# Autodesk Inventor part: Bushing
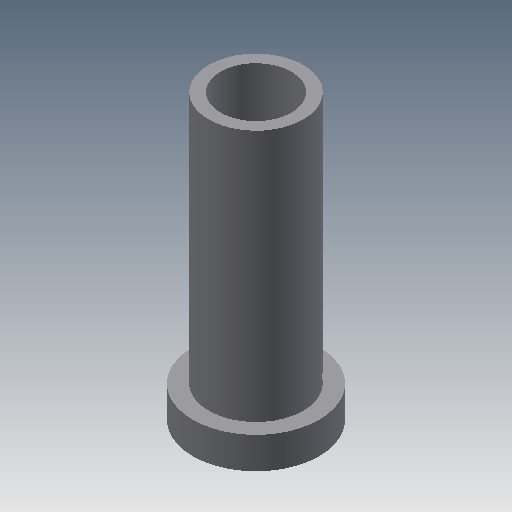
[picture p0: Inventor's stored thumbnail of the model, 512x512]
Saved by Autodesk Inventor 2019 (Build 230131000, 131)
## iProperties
Shininess: 77.0
Length Units: 11269
Angle Units: 11279
Time Units: 11290
Mass Units: 11283
Length Display Precision: 3
Angle Display Precision: 2
Created: 2002-02
Part Number: Bushing
Document SubType Name: Modeling
Designer: ***
Density: 1 g/cm^3
Material: Generic
Appearance: Default
Density: 0.0
Volumn: 0.0
Area: 0.0
PropertySet Name: Model Information
Control State: 0
Master: False
Checked Out: False
Author: ***
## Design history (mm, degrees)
sketch "Sketch1"
  geometry: L1 (6.25, 50.44)-(6.25, 5.44); L2 (6.25, 5.44)-(10.625, 5.44); L3 (10.625, 5.44)-(10.625, 10.44); L4 (10.625, 10.44)-(8.125, 10.44); L5 (8.125, 10.44)-(8.125, 50.44); L6 (8.125, 50.44)-(6.25, 50.44); L7 (0.625, 34.884)-(0.625, 0)
  constraints: 14 end point, 4 parallel, 2 perpendicular, 1 vertical
  dimensions: "d0" = 20 diameter of L3 L7; "d1" = 11.25 diameter of L1 L7; "d2" = 15 diameter of L5 L7; "d4" = 5 distance of L2.end L3.end; "d5" = 45 distance of L1.start L1.end
revolve "Revolution1" sketch "Sketch1" stored, may be unused: angle "d3" = 90 deg
body "Solid1"
